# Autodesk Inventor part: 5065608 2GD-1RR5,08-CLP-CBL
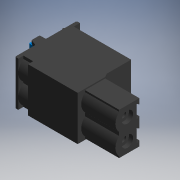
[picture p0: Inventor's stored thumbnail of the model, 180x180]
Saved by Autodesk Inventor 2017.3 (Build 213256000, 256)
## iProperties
Part Number: 5065608 2GD-1RR5,08-CLP-CBL
Material: Generic
Catalog Web Link: www.cadenas.de
Description: NEKM-C6 (p)-Terminal strip
Vendor: FESTO
Document SubType Name: Modeling
Designer: partserver
Manufacturer: FESTO
Mass: 2.55188 g
Surface Area: 17.4369 cm^2
Volume: 2.55188 cm^3
Density: 1 g/cm^3
Appearance: PSOLRGB-80-80-80
Category: PARTsolutions
Company: FESTO
Title: 5065608 2GD-1RR5,08-CLP-CBL
Author: Cadenas PARTsolutions
Comments: Terminal strip
PSOL_IDENT_0: {$CADENAS_DATA\23d-libs\festo\parts\n\nekm\parts\nekm_c6_parts.prj},200 {VTYP=3D},{NB=5065608 2GD-1R
PSOL_IDENT_1: R5,08-CLP-CBL},{LINA=5065608 2GD-1RR5,08-CLP-CBL},{NN=NEKM-C6 (p)},{DATE=16.05.2019 05:36:58},{GEOMD
PSOL_IDENT_2: ATE=16.05.2019 05:36:56},{VERSION=},{LINEID=110},{WBVAR=},{WBNUMERIC=}  {NB=5065608 2GD-1RR5,08-CLP-
PSOL_IDENT_3: CBL},{LINA=5065608 2GD-1RR5,08-CLP-CBL},{KT=DUMMY},{TNR=5065608},{TYP=2GD-1RR5,08-CLP-CBL},{VERS=2},
PSOL_IDENT_4: {N=2},{L=10.780},{L1=2.850}
NB: 5065608 2GD-1RR5,08-CLP-CBL
NN: NEKM-C6 (p)
NT: Terminal strip
NBSYN: $TNR. $TYP.
LINA: 5065608 2GD-1RR5,08-CLP-CBL
CATALOG: Festo
TNR: 5065608
TYP: 2GD-1RR5,08-CLP-CBL
VERS: 2
N: 2
L: 10.78
L1: 2.85
SUPPLIER: FESTO
ARTICLENO: 5065608 2GD-1RR5,08-CLP-CBL
BOMINFO: 5065608 2GD-1RR5,08-CLP-CBL
CREATOR: CADENAS GmbH
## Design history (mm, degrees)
sketch "Sketch_1"
  geometry: L1 (0, 6)-(0, -7.5); L2 (0, -7.5)-(14.43, -7.5); L3 (14.73, -7.2)-(14.73, 4.1); L4 (14.73, 4.5)-(14.73, 7.2); L5 (14.43, 7.5)-(13.93, 7.5); L6 (13.93, 7.5)-(13.93, 6); L7 (13.93, 6)-(0, 6); A1 r 0.3 centre (14.43, -7.2) between (14.43, -7.5) and (14.73, -7.2); A2 r 0.2 centre (14.73, 4.3) between (14.73, 4.1) and (14.73, 4.5); A3 r 0.3 centre (14.43, 7.2) between (14.73, 7.2) and (14.43, 7.5)
  constraints: 14 end point, 6 point on circle, 3 centre point
extrude "Extrusion1" join sketch "Sketch_1" stored distance "d0" = 10.78; taper "d1" = 0 deg
sketch "Sketch_2"
  geometry: L1 (14.73, 0.2)-(14.73, -2.756); L2 (14.927, -2.474)-(16.033, -2.072); L3 (16.23, -1.79)-(16.23, -0.3); L4 (15.93, 0)-(14.93, 0); A1 r 0.3 centre (15.03, -2.756) between (14.927, -2.474) and (14.73, -2.756); A2 r 0.3 centre (15.93, -1.79) between (16.033, -2.072) and (16.23, -1.79); A3 r 0.3 centre (15.93, -0.3) between (16.23, -0.3) and (15.93, 0); A4 r 0.2 centre (14.93, 0.2) between (14.73, 0.2) and (14.93, 0)
  constraints: 8 end point, 8 point on circle, 4 centre point
extrude "Extrusion2" join sketch "Sketch_2" distance "d2" = 0.8; taper "d3" = 0 deg
pattern_linear "Rectangular Pattern1" dims "d6" = 9.98, "d9" = 0
sketch "Sketch_40"
  geometry: L1 (14.73, 0.2)-(14.73, -2.756); L2 (14.927, -2.474)-(16.033, -2.072); L3 (16.23, -1.79)-(16.23, -0.3); L4 (15.93, 0)-(14.93, 0); A1 r 0.3 centre (15.03, -2.756) between (14.927, -2.474) and (14.73, -2.756); A2 r 0.3 centre (15.93, -1.79) between (16.033, -2.072) and (16.23, -1.79); A3 r 0.3 centre (15.93, -0.3) between (16.23, -0.3) and (15.93, 0); A4 r 0.2 centre (14.93, 0.2) between (14.73, 0.2) and (14.93, 0)
  constraints: 8 end point, 8 point on circle, 4 centre point
extrude "Extrusion3" join sketch "Sketch_40" distance "d10" = 0.98; taper "d11" = 0 deg
sketch "Sketch_6"
  geometry: L1 (14.73, -2.075)-(16.6, -2.075); L2 (16.8, -1.875)-(16.8, -1.76); L3 (16.604, -1.516)-(15.936, -1.368); L4 (15.936, -0.782)-(16.604, -0.634); L5 (16.8, -0.39)-(16.8, -0.275); L6 (16.6, -0.075)-(14.73, -0.075); L7 (14.73, -0.075)-(14.73, -2.075); A1 r 0.2 centre (16.6, -1.875) between (16.6, -2.075) and (16.8, -1.875); A2 r 0.25 centre (16.55, -1.76) between (16.8, -1.76) and (16.604, -1.516); A3 r 0.3 centre (16.001, -1.075) between (15.936, -0.782) and (15.936, -1.368); A4 r 0.25 centre (16.55, -0.39) between (16.604, -0.634) and (16.8, -0.39); A5 r 0.2 centre (16.6, -0.275) between (16.8, -0.275) and (16.6, -0.075)
  constraints: 14 end point, 10 point on circle, 5 centre point
extrude "Extrusion4" join sketch "Sketch_6" distance "d12" = 3.9; taper "d13" = 0 deg
pattern_linear "Rectangular Pattern2" dims "d16" = 5.08, "d19" = 0
sketch "Sketch_8"
  geometry: L1 (14.73, -2.74)-(11.73, -2.74); L2 (11.73, -2.74)-(11.73, -0.74); L3 (11.73, -0.74)-(14.53, -0.74); L4 (14.73, -0.54)-(14.73, -2.74); L5 (14.73, -2.74)-(11.73, -2.74); A1 r 0.2 centre (14.53, -0.54) between (14.53, -0.74) and (14.73, -0.54)
  constraints: 10 end point, 2 point on circle, 1 centre point
revolve "Revolution1" sketch "Sketch_8" stored, may be unused: angle "d20" = 360 deg
pattern_linear "Rectangular Pattern3" dims "d23" = 5.08, "d26" = 0
sketch "Sketch_10"
  geometry: L1 (-4.831, 6)-(-0.249, 6); A1 r 2.5 centre (-2.54, 5) between (-0.249, 6) and (-4.831, 6)
  constraints: 2 end point, 2 point on circle, 1 centre point
extrude "Extrusion5" join sketch "Sketch_10" distance "d27" = 9.7; taper "d28" = 0 deg
pattern_linear "Rectangular Pattern4" dims "d31" = 5.08, "d34" = 0
sketch "Sketch_12"
  geometry: L1 (2, 7.5)-(2, 6); L2 (2, 6)-(4.23, 6); L3 (4.23, 6)-(5.73, 7.5); L4 (5.73, 7.5)-(2, 7.5)
  constraints: 8 end point
extrude "Extrusion6" cut sketch "Sketch_12" stored distance "d35" = 10.78; taper "d36" = 0 deg
sketch "Sketch_13"
  geometry: L1 (-3.715, 5.775)-(-3.715, 4.6); L2 (-3.715, 4.6)-(-1.365, 4.6); L3 (-1.365, 4.6)-(-1.365, 5.775); A1 r 1.175 centre (-2.54, 5.775) between (-1.365, 5.775) and (-3.715, 5.775)
  constraints: 6 end point, 2 point on circle, 1 centre point
extrude "Extrusion7" cut sketch "Sketch_13" distance "d37" = 9.325; taper "d38" = 0 deg
pattern_linear "Rectangular Pattern5" dims "d41" = 5.08, "d44" = 0
sketch "Sketch_15"
  geometry: L1 (5.405, -3.715)-(6.58, -3.715); L2 (6.58, -3.715)-(6.58, -1.365); L3 (6.58, -1.365)-(5.405, -1.365); A1 r 1.175 centre (5.405, -2.54) between (5.405, -1.365) and (5.405, -3.715)
  constraints: 6 end point, 2 point on circle, 1 centre point
extrude "Extrusion8" cut sketch "Sketch_15" distance "d45" = 2.9; taper "d46" = 0 deg
pattern_linear "Rectangular Pattern6" dims "d49" = 5.08, "d52" = 0
sketch "Sketch_17"
  geometry: L1 (-2.54, 6)-(-2.54, 6.3); L2 (-2.09, 6)-(-2.54, 6); L3 (-2.54, 6)-(-2.54, 6.3); A1 r 0.5 centre (-2.548, 5.8) between (-2.09, 6) and (-2.54, 6.3)
  constraints: 6 end point, 2 point on circle, 1 centre point
revolve "Revolution2" sketch "Sketch_17" stored, may be unused: angle "d53" = 360 deg
pattern_linear "Rectangular Pattern7" dims "d56" = 5.08, "d59" = 0
sketch "Sketch_25"
  geometry: L1 (-0.5, -0.795)-(-0.5, -7.5); L2 (-0.5, -7.5)-(0, -7.5); L3 (0, -7.5)-(0, 0.071); L4 (0, 0.071)-(-0.5, -0.795)
  constraints: 8 end point
extrude "Extrusion9" join sketch "Sketch_25" stored distance "d60" = 10.78; taper "d61" = 0 deg
sketch "Sketch_35"
  geometry: L1 (-5.08, -5.71)-(-4.661, -5.71); L2 (-0.419, -5.71)-(0.419, -5.71); L3 (4.661, -5.71)-(5.08, -5.71); L4 (5.08, -5.71)-(5.08, -0.795); L5 (5.08, -0.795)-(3.797, -0.795); L6 (3.797, -0.795)-(4.19, -1.475); L7 (4.19, -1.475)-(0.893, -1.475); L8 (0.893, -1.475)-(1.286, -0.795); L9 (1.286, -0.795)-(-1.283, -0.795); L10 (-1.283, -0.795)-(-0.89, -1.475); L11 (-0.89, -1.475)-(-4.187, -1.475); L12 (-4.187, -1.475)-(-3.794, -0.795); L13 (-3.794, -0.795)-(-5.08, -0.795); L14 (-5.08, -0.795)-(-5.08, -5.71); A1 r 2.915 centre (-2.54, -3.71) between (-4.661, -5.71) and (-0.419, -5.71); A2 r 2.915 centre (2.54, -3.71) between (0.419, -5.71) and (4.661, -5.71)
  constraints: 28 end point, 4 point on circle, 2 centre point
extrude "Extrusion10" join sketch "Sketch_35" distance "d62" = 8.3; taper "d63" = 0 deg
sketch "Sketch13"
  geometry: 1 further point
hole "Hole1" sketch "Sketch13" at (2.54, -3.71) diameter "d64" = 1.4; stored, may be unused: countersink angle "d68" = 90 deg, drill point angle "d70" = 0 deg; dims "d65" = 6, "d66" = 2.8, "d67" = 1, "d69" = 2
pattern_linear "Rectangular Pattern8" dims "d73" = 5.08, "d76" = 0
sketch "Sketch_30"
  geometry: L1 (-4.86, 0.947)-(-4.164, 0.545); L2 (-3.802, 0.593)-(-3.53, 0.865); L3 (-3.53, 0.865)-(-0.326, 1.005); L4 (-0.5, 0.206)-(-0.5, -1); L5 (-0.5, -1)-(0.5, -1); L6 (0.5, -1)-(0.5, 3.353); L7 (0.5, 3.353)-(0, 3.353); L8 (-0.233, 3.061)-(-3.754, 2.248); L9 (-4.115, 2.048)-(-4.901, 1.262); A1 r 0.2 centre (-4.76, 1.12) between (-4.901, 1.262) and (-4.86, 0.947); A2 r 0.3 centre (-4.014, 0.805) between (-4.164, 0.545) and (-3.802, 0.593); A3 r 0.3 centre (-0.3, 0.706) between (-0.3, 0.406) and (-0.326, 1.005); A4 r 0.2 centre (-0.3, 0.206) between (-0.3, 0.406) and (-0.5, 0.206); A5 r 0.3 centre (-0.3, 3.353) between (-0.233, 3.061) and (0, 3.353); A6 r 0.75 centre (-3.585, 1.517) between (-3.754, 2.248) and (-4.115, 2.048)
  constraints: 18 end point, 12 point on circle, 6 centre point
extrude "Extrusion11" join sketch "Sketch_30" distance "d77" = 1.6; taper "d78" = 0 deg
sketch "Sketch_27"
  geometry: L1 (-5.39, -8.25)-(5.39, -8.25); L2 (5.39, -8.25)-(5.39, -6.25); L3 (5.39, -6.25)-(4.698, -6.25); L4 (-0.018, -6.25)-(-0.382, -6.25); L5 (-5.098, -6.25)-(-5.39, -6.25); L6 (-5.39, -6.25)-(-5.39, -8.25); A1 r 2.85 centre (2.34, -4.65) between (-0.018, -6.25) and (4.698, -6.25); A2 r 2.85 centre (-2.74, -4.65) between (-5.098, -6.25) and (-0.382, -6.25)
  constraints: 12 end point, 4 point on circle, 2 centre point
extrude "Extrusion12" cut sketch "Sketch_27" distance "d79" = 2.35; taper "d80" = 0 deg
node "ANBAU_XY"
node "ANBAU_YZ"
node "ANBAU_ZX"
node "ANBAU_X"
node "ANBAU_Y"
node "ANBAU_Z"
node "ANBAU_Center"
node "CP1_XY"
node "CP1_YZ"
node "CP1_ZX"
node "CP1_X"
node "CP1_Y"
node "CP1_Z"
node "CP1_Center"
body "Solid1"
other parameters: "d81" = 0
